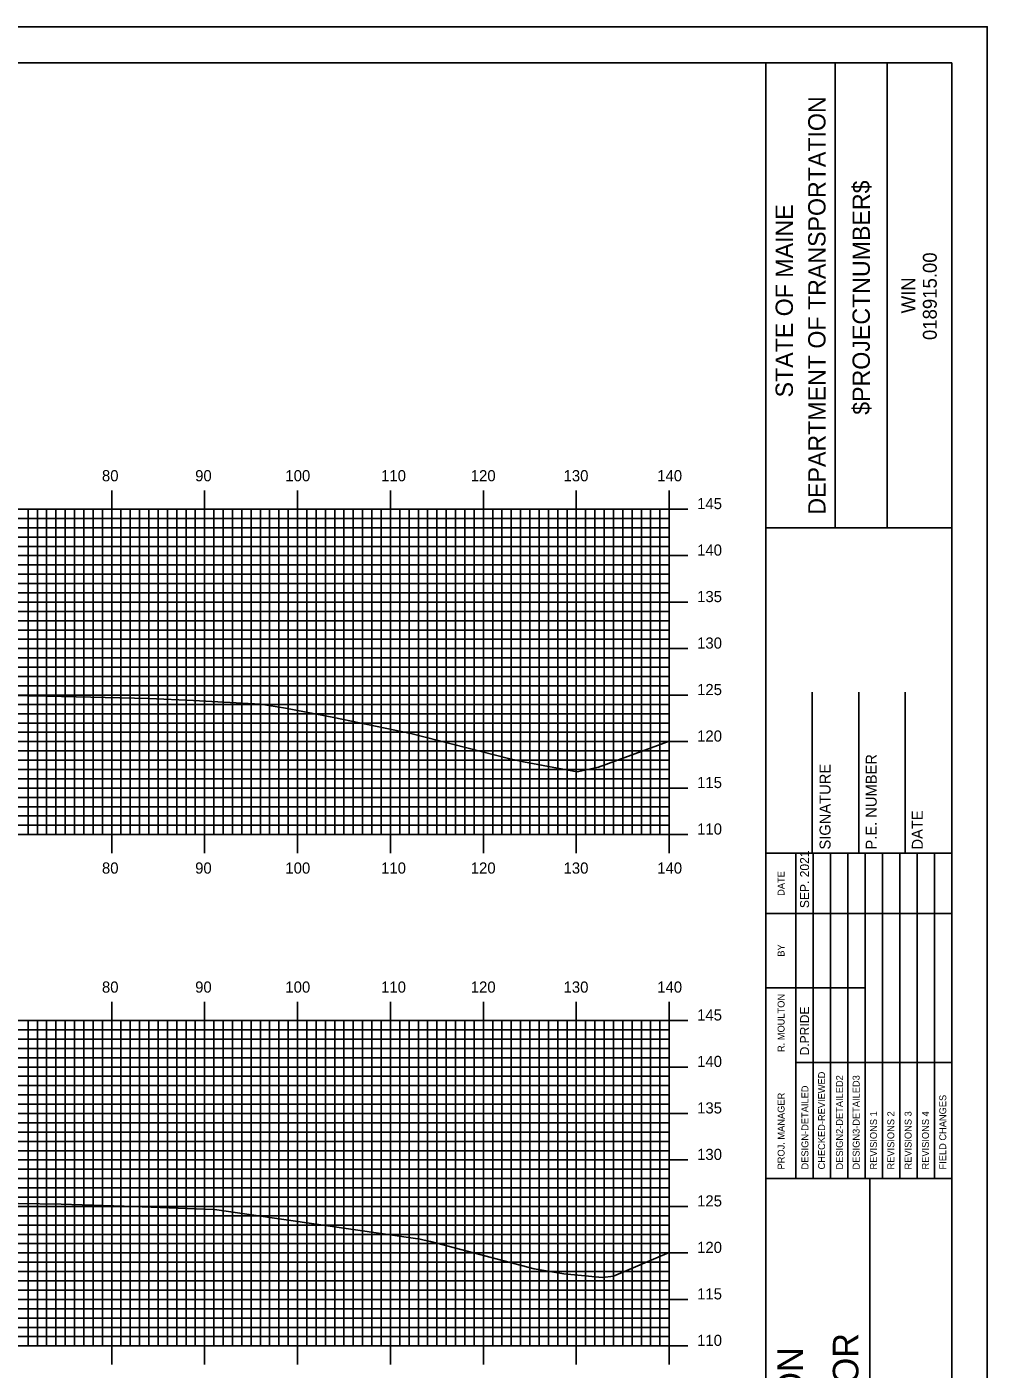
# Model space of a CAD drawing. Extents: x 853107 to 853450, y 366605 to 366825.
# Drawn here: x 853343.4 to 853446.7, y 366680.6 to 366824.9 of the extents above; entities that cross this region are included whole.
import ezdxf

# ---------------------------------------------------------------- set-up
doc = ezdxf.new("R2010")
doc.units = 0
for name, color, linetype in [('BORDER', 7, 'Continuous'), ('H_V ANNOTATION', 7, 'Continuous'), ('MAJOR', 7, 'Continuous'), ('MINOR', 7, 'Continuous'), ('PLOT BOUNDARY', 7, 'Continuous'), ('S_Roadway_Centerline', 7, 'Continuous')]:
    doc.layers.add(name, color=color, linetype=linetype)

msp = doc.modelspace()

# ---------------------------------------------------------------- linework, layer by layer
at = {"layer": 'BORDER'}
for p, q in [((853422.9, 366611.06), (853422.9, 366821.06)), ((853430.36, 366771.05), (853430.36, 366821.05)), ((853435.95, 366771.05), (853435.95, 366821.05)), ((853422.91, 366771.04), (853442.9, 366771.04)), ((853427.9, 366736.06), (853427.9, 366753.36)), ((853432.9, 366736.06), (853432.9, 366753.36)), ((853437.9, 366736.06), (853437.9, 366753.36)), ((853422.9, 366736.06), (853442.9, 366736.06)), ((853422.9, 366701.06), (853442.9, 366701.06)), ((853434.09, 366631.06), (853434.09, 366701.06))]:
    msp.add_line(p, q, dxfattribs=at)
msp.add_lwpolyline([(853122.9, 366611.06), (853442.9, 366611.06), (853442.9, 366821.06), (853122.9, 366821.06)], close=True, dxfattribs=at)
for points in [[(853426.13, 366729.56), (853426.13, 366736.06)], [(853428, 366701.07), (853428, 366736.06)], [(853429.86, 366736.06), (853429.86, 366701.07)], [(853431.73, 366701.07), (853431.73, 366736.06)], [(853433.59, 366701.07), (853433.59, 366736.06)], [(853435.45, 366701.07), (853435.45, 366736.06)], [(853437.32, 366701.07), (853437.32, 366736.06)], [(853439.18, 366701.07), (853439.18, 366736.06)], [(853441.04, 366701.07), (853441.04, 366736.06)], [(853426.14, 366701.07), (853426.14, 366734.65)], [(853422.9, 366729.56), (853442.9, 366729.56)], [(853422.9, 366721.56), (853426.14, 366721.56)], [(853426.13, 366721.56), (853433.59, 366721.56)], [(853426.13, 366713.56), (853442.9, 366713.56)]]:
    msp.add_lwpolyline(points, dxfattribs=at)
at = {"layer": 'MAJOR'}
for p, q in [((853352.5, 366775.06), (853352.5, 366773.06)), ((853362.5, 366775.06), (853362.5, 366773.06)), ((853372.5, 366775.06), (853372.5, 366773.06)), ((853382.5, 366775.06), (853382.5, 366773.06)), ((853392.5, 366775.06), (853392.5, 366773.06)), ((853402.5, 366775.06), (853402.5, 366773.06)), ((853412.5, 366775.06), (853412.5, 366773.06)), ((853132.5, 366773.06), (853412.5, 366773.06)), ((853132.5, 366773.06), (853412.5, 366773.06)), ((853352.5, 366738.06), (853352.5, 366773.06)), ((853362.5, 366738.06), (853362.5, 366773.06)), ((853372.5, 366738.06), (853372.5, 366773.06)), ((853382.5, 366738.06), (853382.5, 366773.06)), ((853392.5, 366738.06), (853392.5, 366773.06)), ((853402.5, 366738.06), (853402.5, 366773.06)), ((853414.51, 366773.06), (853410.5, 366773.06)), ((853412.5, 366738.06), (853412.5, 366773.06)), ((853412.5, 366738.06), (853412.5, 366773.06)), ((853132.5, 366768.06), (853412.5, 366768.06)), ((853414.51, 366768.06), (853410.5, 366768.06)), ((853132.5, 366763.06), (853412.5, 366763.06)), ((853414.51, 366763.06), (853410.5, 366763.06)), ((853132.5, 366758.06), (853412.5, 366758.06)), ((853414.51, 366758.06), (853410.5, 366758.06)), ((853132.5, 366753.06), (853412.5, 366753.06)), ((853414.51, 366753.06), (853410.5, 366753.06)), ((853132.5, 366748.06), (853412.5, 366748.06)), ((853414.51, 366748.06), (853410.5, 366748.06)), ((853132.5, 366743.06), (853412.5, 366743.06)), ((853414.51, 366743.06), (853410.5, 366743.06)), ((853132.5, 366738.06), (853412.5, 366738.06)), ((853132.5, 366738.06), (853412.5, 366738.06)), ((853352.5, 366736.05), (853352.5, 366738.06)), ((853362.5, 366736.05), (853362.5, 366738.06)), ((853372.5, 366736.05), (853372.5, 366738.06)), ((853382.5, 366736.05), (853382.5, 366738.06)), ((853392.5, 366736.05), (853392.5, 366738.06)), ((853402.5, 366736.05), (853402.5, 366738.06)), ((853414.51, 366738.06), (853410.5, 366738.06)), ((853412.5, 366736.05), (853412.5, 366738.06)), ((853352.5, 366720.06), (853352.5, 366718.06)), ((853362.5, 366720.06), (853362.5, 366718.06)), ((853372.5, 366720.06), (853372.5, 366718.06)), ((853382.5, 366720.06), (853382.5, 366718.06)), ((853392.5, 366720.06), (853392.5, 366718.06)), ((853402.5, 366720.06), (853402.5, 366718.06)), ((853412.5, 366720.06), (853412.5, 366718.06)), ((853132.5, 366718.06), (853412.5, 366718.06)), ((853132.5, 366718.06), (853412.5, 366718.06)), ((853352.5, 366683.06), (853352.5, 366718.06)), ((853362.5, 366683.06), (853362.5, 366718.06)), ((853372.5, 366683.06), (853372.5, 366718.06)), ((853382.5, 366683.06), (853382.5, 366718.06)), ((853392.5, 366683.06), (853392.5, 366718.06)), ((853402.5, 366683.06), (853402.5, 366718.06)), ((853414.51, 366718.06), (853410.5, 366718.06)), ((853412.5, 366683.06), (853412.5, 366718.06)), ((853412.5, 366683.06), (853412.5, 366718.06)), ((853132.5, 366713.06), (853412.5, 366713.06)), ((853414.51, 366713.06), (853410.5, 366713.06)), ((853132.5, 366708.06), (853412.5, 366708.06)), ((853414.51, 366708.06), (853410.5, 366708.06)), ((853132.5, 366703.06), (853412.5, 366703.06)), ((853414.51, 366703.06), (853410.5, 366703.06)), ((853132.5, 366698.06), (853412.5, 366698.06)), ((853414.51, 366698.06), (853410.5, 366698.06)), ((853132.5, 366693.06), (853412.5, 366693.06)), ((853414.51, 366693.06), (853410.5, 366693.06)), ((853132.5, 366688.06), (853412.5, 366688.06)), ((853414.51, 366688.06), (853410.5, 366688.06)), ((853132.5, 366683.06), (853412.5, 366683.06)), ((853132.5, 366683.06), (853412.5, 366683.06)), ((853352.5, 366681.05), (853352.5, 366683.06)), ((853362.5, 366681.05), (853362.5, 366683.06)), ((853372.5, 366681.05), (853372.5, 366683.06)), ((853382.5, 366681.05), (853382.5, 366683.06)), ((853392.5, 366681.05), (853392.5, 366683.06)), ((853402.5, 366681.05), (853402.5, 366683.06)), ((853414.51, 366683.06), (853410.5, 366683.06)), ((853412.5, 366681.05), (853412.5, 366683.06))]:
    msp.add_line(p, q, dxfattribs=at)
at = {"layer": 'MINOR'}
for p, q in [((853343.5, 366738.06), (853343.5, 366773.06)), ((853344.5, 366738.06), (853344.5, 366773.06)), ((853345.5, 366738.06), (853345.5, 366773.06)), ((853346.5, 366738.06), (853346.5, 366773.06)), ((853347.5, 366738.06), (853347.5, 366773.06)), ((853348.5, 366738.06), (853348.5, 366773.06)), ((853349.5, 366738.06), (853349.5, 366773.06)), ((853350.5, 366738.06), (853350.5, 366773.06)), ((853351.5, 366738.06), (853351.5, 366773.06)), ((853353.5, 366738.06), (853353.5, 366773.06)), ((853354.5, 366738.06), (853354.5, 366773.06)), ((853355.5, 366738.06), (853355.5, 366773.06)), ((853356.5, 366738.06), (853356.5, 366773.06)), ((853357.5, 366738.06), (853357.5, 366773.06)), ((853358.5, 366738.06), (853358.5, 366773.06)), ((853359.5, 366738.06), (853359.5, 366773.06)), ((853360.5, 366738.06), (853360.5, 366773.06)), ((853361.5, 366738.06), (853361.5, 366773.06)), ((853363.5, 366738.06), (853363.5, 366773.06)), ((853364.5, 366738.06), (853364.5, 366773.06)), ((853365.5, 366738.06), (853365.5, 366773.06)), ((853366.5, 366738.06), (853366.5, 366773.06)), ((853367.5, 366738.06), (853367.5, 366773.06)), ((853368.5, 366738.06), (853368.5, 366773.06)), ((853369.5, 366738.06), (853369.5, 366773.06)), ((853370.5, 366738.06), (853370.5, 366773.06)), ((853371.5, 366738.06), (853371.5, 366773.06)), ((853373.5, 366738.06), (853373.5, 366773.06)), ((853374.5, 366738.06), (853374.5, 366773.06)), ((853375.5, 366738.06), (853375.5, 366773.06)), ((853376.5, 366738.06), (853376.5, 366773.06)), ((853377.5, 366738.06), (853377.5, 366773.06)), ((853378.5, 366738.06), (853378.5, 366773.06)), ((853379.5, 366738.06), (853379.5, 366773.06)), ((853380.5, 366738.06), (853380.5, 366773.06)), ((853381.5, 366738.06), (853381.5, 366773.06)), ((853383.5, 366738.06), (853383.5, 366773.06)), ((853384.5, 366738.06), (853384.5, 366773.06)), ((853385.5, 366738.06), (853385.5, 366773.06)), ((853386.5, 366738.06), (853386.5, 366773.06)), ((853387.5, 366738.06), (853387.5, 366773.06)), ((853388.5, 366738.06), (853388.5, 366773.06)), ((853389.5, 366738.06), (853389.5, 366773.06)), ((853390.5, 366738.06), (853390.5, 366773.06)), ((853391.5, 366738.06), (853391.5, 366773.06)), ((853393.5, 366738.06), (853393.5, 366773.06)), ((853394.5, 366738.06), (853394.5, 366773.06)), ((853395.5, 366738.06), (853395.5, 366773.06)), ((853396.5, 366738.06), (853396.5, 366773.06)), ((853397.5, 366738.06), (853397.5, 366773.06)), ((853398.5, 366738.06), (853398.5, 366773.06)), ((853399.5, 366738.06), (853399.5, 366773.06)), ((853400.5, 366738.06), (853400.5, 366773.06)), ((853401.5, 366738.06), (853401.5, 366773.06)), ((853403.5, 366738.06), (853403.5, 366773.06)), ((853404.5, 366738.06), (853404.5, 366773.06)), ((853405.5, 366738.06), (853405.5, 366773.06)), ((853406.5, 366738.06), (853406.5, 366773.06)), ((853407.5, 366738.06), (853407.5, 366773.06)), ((853408.5, 366738.06), (853408.5, 366773.06)), ((853409.5, 366738.06), (853409.5, 366773.06)), ((853410.5, 366738.06), (853410.5, 366773.06)), ((853411.5, 366738.06), (853411.5, 366773.06)), ((853132.5, 366772.06), (853412.5, 366772.06)), ((853412.5, 366772.06), (853410.5, 366772.06)), ((853132.5, 366771.06), (853412.5, 366771.06)), ((853132.5, 366770.06), (853412.5, 366770.06)), ((853412.5, 366771.06), (853410.5, 366771.06)), ((853412.5, 366770.06), (853410.5, 366770.06)), ((853132.5, 366769.06), (853412.5, 366769.06)), ((853412.5, 366769.06), (853410.5, 366769.06)), ((853132.5, 366767.06), (853412.5, 366767.06)), ((853412.5, 366767.06), (853410.5, 366767.06)), ((853132.5, 366766.06), (853412.5, 366766.06)), ((853412.5, 366766.06), (853410.5, 366766.06)), ((853132.5, 366765.06), (853412.5, 366765.06)), ((853132.5, 366764.06), (853412.5, 366764.06)), ((853412.5, 366765.06), (853410.5, 366765.06)), ((853412.5, 366764.06), (853410.5, 366764.06)), ((853132.5, 366762.06), (853412.5, 366762.06)), ((853132.5, 366761.06), (853412.5, 366761.06)), ((853412.5, 366762.06), (853410.5, 366762.06)), ((853412.5, 366761.06), (853410.5, 366761.06)), ((853132.5, 366760.06), (853412.5, 366760.06)), ((853412.5, 366760.06), (853410.5, 366760.06)), ((853132.5, 366759.06), (853412.5, 366759.06)), ((853412.5, 366759.06), (853410.5, 366759.06)), ((853132.5, 366757.06), (853412.5, 366757.06)), ((853412.5, 366757.06), (853410.5, 366757.06)), ((853132.5, 366756.06), (853412.5, 366756.06)), ((853412.5, 366756.06), (853410.5, 366756.06)), ((853132.5, 366755.06), (853412.5, 366755.06)), ((853132.5, 366754.06), (853412.5, 366754.06)), ((853412.5, 366755.06), (853410.5, 366755.06)), ((853412.5, 366754.06), (853410.5, 366754.06)), ((853132.5, 366752.06), (853412.5, 366752.06)), ((853132.5, 366751.06), (853412.5, 366751.06)), ((853412.5, 366752.06), (853410.5, 366752.06)), ((853412.5, 366751.06), (853410.5, 366751.06)), ((853132.5, 366750.06), (853412.5, 366750.06)), ((853412.5, 366750.06), (853410.5, 366750.06)), ((853132.5, 366749.06), (853412.5, 366749.06)), ((853412.5, 366749.06), (853410.5, 366749.06)), ((853132.5, 366747.06), (853412.5, 366747.06)), ((853412.5, 366747.06), (853410.5, 366747.06)), ((853132.5, 366746.06), (853412.5, 366746.06)), ((853412.5, 366746.06), (853410.5, 366746.06)), ((853132.5, 366745.06), (853412.5, 366745.06)), ((853132.5, 366744.06), (853412.5, 366744.06)), ((853412.5, 366745.06), (853410.5, 366745.06)), ((853412.5, 366744.06), (853410.5, 366744.06)), ((853132.5, 366742.06), (853412.5, 366742.06)), ((853132.5, 366741.06), (853412.5, 366741.06)), ((853412.5, 366742.06), (853410.5, 366742.06)), ((853412.5, 366741.06), (853410.5, 366741.06)), ((853132.5, 366740.06), (853412.5, 366740.06)), ((853412.5, 366740.06), (853410.5, 366740.06)), ((853132.5, 366739.06), (853412.5, 366739.06)), ((853412.5, 366739.06), (853410.5, 366739.06)), ((853343.5, 366683.06), (853343.5, 366718.06)), ((853344.5, 366683.06), (853344.5, 366718.06)), ((853345.5, 366683.06), (853345.5, 366718.06)), ((853346.5, 366683.06), (853346.5, 366718.06)), ((853347.5, 366683.06), (853347.5, 366718.06)), ((853348.5, 366683.06), (853348.5, 366718.06)), ((853349.5, 366683.06), (853349.5, 366718.06)), ((853350.5, 366683.06), (853350.5, 366718.06)), ((853351.5, 366683.06), (853351.5, 366718.06)), ((853353.5, 366683.06), (853353.5, 366718.06)), ((853354.5, 366683.06), (853354.5, 366718.06)), ((853355.5, 366683.06), (853355.5, 366718.06)), ((853356.5, 366683.06), (853356.5, 366718.06)), ((853357.5, 366683.06), (853357.5, 366718.06)), ((853358.5, 366683.06), (853358.5, 366718.06)), ((853359.5, 366683.06), (853359.5, 366718.06)), ((853360.5, 366683.06), (853360.5, 366718.06)), ((853361.5, 366683.06), (853361.5, 366718.06)), ((853363.5, 366683.06), (853363.5, 366718.06)), ((853364.5, 366683.06), (853364.5, 366718.06)), ((853365.5, 366683.06), (853365.5, 366718.06)), ((853366.5, 366683.06), (853366.5, 366718.06)), ((853367.5, 366683.06), (853367.5, 366718.06)), ((853368.5, 366683.06), (853368.5, 366718.06)), ((853369.5, 366683.06), (853369.5, 366718.06)), ((853370.5, 366683.06), (853370.5, 366718.06)), ((853371.5, 366683.06), (853371.5, 366718.06)), ((853373.5, 366683.06), (853373.5, 366718.06)), ((853374.5, 366683.06), (853374.5, 366718.06)), ((853375.5, 366683.06), (853375.5, 366718.06)), ((853376.5, 366683.06), (853376.5, 366718.06)), ((853377.5, 366683.06), (853377.5, 366718.06)), ((853378.5, 366683.06), (853378.5, 366718.06)), ((853379.5, 366683.06), (853379.5, 366718.06)), ((853380.5, 366683.06), (853380.5, 366718.06)), ((853381.5, 366683.06), (853381.5, 366718.06)), ((853383.5, 366683.06), (853383.5, 366718.06)), ((853384.5, 366683.06), (853384.5, 366718.06)), ((853385.5, 366683.06), (853385.5, 366718.06)), ((853386.5, 366683.06), (853386.5, 366718.06)), ((853387.5, 366683.06), (853387.5, 366718.06)), ((853388.5, 366683.06), (853388.5, 366718.06)), ((853389.5, 366683.06), (853389.5, 366718.06)), ((853390.5, 366683.06), (853390.5, 366718.06)), ((853391.5, 366683.06), (853391.5, 366718.06)), ((853393.5, 366683.06), (853393.5, 366718.06)), ((853394.5, 366683.06), (853394.5, 366718.06)), ((853395.5, 366683.06), (853395.5, 366718.06)), ((853396.5, 366683.06), (853396.5, 366718.06)), ((853397.5, 366683.06), (853397.5, 366718.06)), ((853398.5, 366683.06), (853398.5, 366718.06)), ((853399.5, 366683.06), (853399.5, 366718.06)), ((853400.5, 366683.06), (853400.5, 366718.06)), ((853401.5, 366683.06), (853401.5, 366718.06)), ((853403.5, 366683.06), (853403.5, 366718.06)), ((853404.5, 366683.06), (853404.5, 366718.06)), ((853405.5, 366683.06), (853405.5, 366718.06)), ((853406.5, 366683.06), (853406.5, 366718.06)), ((853407.5, 366683.06), (853407.5, 366718.06)), ((853408.5, 366683.06), (853408.5, 366718.06)), ((853409.5, 366683.06), (853409.5, 366718.06)), ((853410.5, 366683.06), (853410.5, 366718.06)), ((853411.5, 366683.06), (853411.5, 366718.06)), ((853132.5, 366717.06), (853412.5, 366717.06)), ((853412.5, 366717.06), (853410.5, 366717.06)), ((853132.5, 366716.06), (853412.5, 366716.06)), ((853132.5, 366715.06), (853412.5, 366715.06)), ((853412.5, 366716.06), (853410.5, 366716.06)), ((853412.5, 366715.06), (853410.5, 366715.06)), ((853132.5, 366714.06), (853412.5, 366714.06)), ((853412.5, 366714.06), (853410.5, 366714.06)), ((853132.5, 366712.06), (853412.5, 366712.06)), ((853412.5, 366712.06), (853410.5, 366712.06)), ((853132.5, 366711.06), (853412.5, 366711.06)), ((853412.5, 366711.06), (853410.5, 366711.06)), ((853132.5, 366710.06), (853412.5, 366710.06)), ((853132.5, 366709.06), (853412.5, 366709.06)), ((853412.5, 366710.06), (853410.5, 366710.06)), ((853412.5, 366709.06), (853410.5, 366709.06)), ((853132.5, 366707.06), (853412.5, 366707.06)), ((853412.5, 366707.06), (853410.5, 366707.06)), ((853132.5, 366706.06), (853412.5, 366706.06)), ((853132.5, 366705.06), (853412.5, 366705.06)), ((853412.5, 366706.06), (853410.5, 366706.06)), ((853412.5, 366705.06), (853410.5, 366705.06)), ((853132.5, 366704.06), (853412.5, 366704.06)), ((853412.5, 366704.06), (853410.5, 366704.06)), ((853132.5, 366702.06), (853412.5, 366702.06)), ((853412.5, 366702.06), (853410.5, 366702.06)), ((853132.5, 366701.06), (853412.5, 366701.06)), ((853412.5, 366701.06), (853410.5, 366701.06)), ((853132.5, 366700.06), (853412.5, 366700.06)), ((853132.5, 366699.06), (853412.5, 366699.06)), ((853412.5, 366700.06), (853410.5, 366700.06)), ((853412.5, 366699.06), (853410.5, 366699.06)), ((853132.5, 366697.06), (853412.5, 366697.06)), ((853132.5, 366696.06), (853412.5, 366696.06)), ((853412.5, 366697.06), (853410.5, 366697.06)), ((853412.5, 366696.06), (853410.5, 366696.06)), ((853132.5, 366695.06), (853412.5, 366695.06)), ((853412.5, 366695.06), (853410.5, 366695.06)), ((853132.5, 366694.06), (853412.5, 366694.06)), ((853412.5, 366694.06), (853410.5, 366694.06)), ((853132.5, 366692.06), (853412.5, 366692.06)), ((853412.5, 366692.06), (853410.5, 366692.06)), ((853132.5, 366691.06), (853412.5, 366691.06)), ((853412.5, 366691.06), (853410.5, 366691.06)), ((853132.5, 366690.06), (853412.5, 366690.06)), ((853132.5, 366689.06), (853412.5, 366689.06)), ((853412.5, 366690.06), (853410.5, 366690.06)), ((853412.5, 366689.06), (853410.5, 366689.06)), ((853132.5, 366687.06), (853412.5, 366687.06)), ((853132.5, 366686.06), (853412.5, 366686.06)), ((853412.5, 366687.06), (853410.5, 366687.06)), ((853412.5, 366686.06), (853410.5, 366686.06)), ((853132.5, 366685.06), (853412.5, 366685.06)), ((853412.5, 366685.06), (853410.5, 366685.06)), ((853132.5, 366684.06), (853412.5, 366684.06)), ((853412.5, 366684.06), (853410.5, 366684.06))]:
    msp.add_line(p, q, dxfattribs=at)
at = {"layer": 'PLOT BOUNDARY'}
msp.add_lwpolyline([(853106.72, 366604.94), (853446.72, 366604.94), (853446.72, 366824.94), (853106.72, 366824.94)], close=True, dxfattribs=at)
at = {"layer": 'S_Roadway_Centerline'}
for points in [[(853341.42, 366753.01), (853345.51, 366752.96), (853356.55, 366752.69), (853361.32, 366752.48), (853368.51, 366752.1), (853371.2, 366751.67), (853376.39, 366750.66), (853384.69, 366748.92), (853395.2, 366746.24), (853396.82, 366745.87), (853402.58, 366744.82), (853404.9, 366745.31), (853411.62, 366747.8), (853412.5, 366748.12)], [(853342.42, 366698.37), (853347.08, 366698.31), (853353.83, 366698.08), (853363.54, 366697.74), (853363.55, 366697.74), (853363.58, 366697.73), (853385.69, 366694.54), (853386.12, 366694.45), (853386.8, 366694.28), (853397.95, 366691.34), (853401.16, 366690.82), (853405.31, 366690.41), (853406.49, 366690.58), (853412.5, 366693.12)]]:
    msp.add_lwpolyline(points, dxfattribs=at)

# ---------------------------------------------------------------- texts
at = {"layer": 'BORDER'}
for s, height, p in [('DEPARTMENT OF TRANSPORTATION', 1.8635, (853429.32, 366772.47)), ('$PROJECTNUMBER$', 1.8635, (853434.09, 366783.21)), ('STATE OF MAINE', 1.8635, (853425.81, 366785.08)), ('018915.00', 1.491, (853441.29, 366791.25)), ('WIN', 1.491, (853438.98, 366794.12)), ('P.E. NUMBER', 1.1811, (853434.83, 366736.45)), ('SIGNATURE', 1.181, (853429.86, 366736.45)), ('DATE', 1.181, (853439.79, 366736.45)), ('SEP. 2021', 0.969, (853427.55, 366730.15)), ('DATE', 0.743, (853424.91, 366731.47)), ('BY', 0.743, (853424.91, 366724.93)), ('R. MOULTON', 0.745, (853424.91, 366714.67)), ('D.PRIDE', 0.969, (853427.55, 366714.31)), ('CHECKED-REVIEWED', 0.7455, (853429.27, 366702.04)), ('DESIGN2-DETAILED2', 0.7455, (853431.2, 366702.04)), ('DESIGN3-DETAILED3', 0.7455, (853432.99, 366702.04)), ('DESIGN-DETAILED', 0.7455, (853427.48, 366702.04)), ('PROJ. MANAGER', 0.7455, (853424.91, 366702.04)), ('FIELD CHANGES', 0.7455, (853442.31, 366702.04)), ('REVISIONS 1', 0.7455, (853434.86, 366702.04)), ('REVISIONS 2', 0.7455, (853436.72, 366702.04)), ('REVISIONS 3', 0.7455, (853438.58, 366702.04)), ('REVISIONS 4', 0.7455, (853440.45, 366702.04)), ('1-395/ROUTE 9 CONNECTOR', 2.7557, (853432.86, 366633.26)), ('BREWER TO EDDINGTON', 2.7557, (853426.89, 366637.46))]:
    msp.add_text(s, height=height, rotation=90, dxfattribs=at).set_placement(p)
at = {"layer": 'H_V ANNOTATION'}
for s, p in [('80', (853351.45, 366776.06)), ('90', (853361.48, 366776.06)), ('100', (853371.19, 366776.06)), ('110', (853381.49, 366776.06)), ('120', (853391.14, 366776.06)), ('130', (853401.13, 366776.06)), ('140', (853411.21, 366776.06)), ('145', (853415.5, 366773.06)), ('140', (853415.5, 366768.06)), ('135', (853415.5, 366763.06)), ('130', (853415.5, 366758.06)), ('125', (853415.5, 366753.06)), ('120', (853415.5, 366748.06)), ('115', (853415.5, 366743.06)), ('110', (853415.5, 366738.06)), ('80', (853351.45, 366733.86)), ('90', (853361.48, 366733.86)), ('100', (853371.19, 366733.86)), ('110', (853381.49, 366733.86)), ('120', (853391.14, 366733.86)), ('130', (853401.13, 366733.86)), ('140', (853411.21, 366733.86)), ('80', (853351.45, 366721.06)), ('90', (853361.48, 366721.06)), ('100', (853371.19, 366721.06)), ('110', (853381.49, 366721.06)), ('120', (853391.14, 366721.06)), ('130', (853401.13, 366721.06)), ('140', (853411.21, 366721.06)), ('145', (853415.5, 366718.06)), ('140', (853415.5, 366713.06)), ('135', (853415.5, 366708.06)), ('130', (853415.5, 366703.06)), ('125', (853415.5, 366698.06)), ('120', (853415.5, 366693.06)), ('115', (853415.5, 366688.06)), ('110', (853415.5, 366683.06))]:
    msp.add_text(s, height=1.2, dxfattribs=at).set_placement(p)

doc.saveas('drawing.dxf')
